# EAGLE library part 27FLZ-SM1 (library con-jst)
CONNECTOR
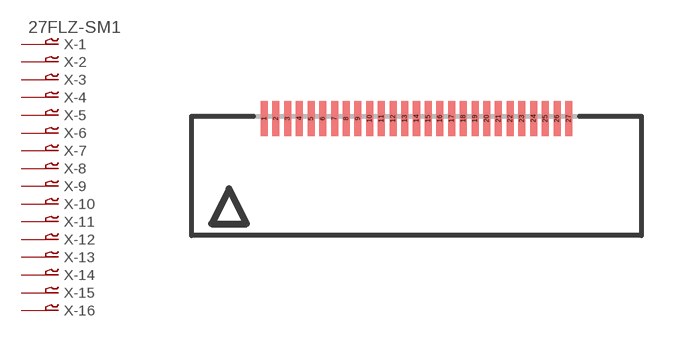
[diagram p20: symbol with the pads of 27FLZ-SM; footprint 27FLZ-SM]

Designator prefix X; gates -1=P-VN -2=P-N -3=P-N -4=P-N -5=P-N -6=P-N -7=P-N -8=P-N -9=P-N -10=P-N -11=P-N -12=P-N -13=P-N -14=P-N -15=P-N -16=P-N -17=P-N -18=P-N -19=P-N -20=P-N -21=P-N -22=P-N -23=P-N -24=P-N -25=P-N -26=P-N -27=P-N

## 27FLZ-SM1 (OC_FARNELL: unknown; OC_NEWARK: unknown)  [27FLZ-SM]
1  -1:1  pas
2  -2:1  pas
3  -3:1  pas
4  -4:1  pas
5  -5:1  pas
6  -6:1  pas
7  -7:1  pas
8  -8:1  pas
9  -9:1  pas
10  -10:1  pas
11  -11:1  pas
12  -12:1  pas
13  -13:1  pas
14  -14:1  pas
15  -15:1  pas
16  -16:1  pas
17  -17:1  pas
18  -18:1  pas
19  -19:1  pas
20  -20:1  pas
21  -21:1  pas
22  -22:1  pas
23  -23:1  pas
24  -24:1  pas
25  -25:1  pas
26  -26:1  pas
27  -27:1  pas

## Footprint 27FLZ-SM (pad centres in mm)
CONNECTOR
smd 0.3 x 1.5: 1 -6.5,2.5; 2 -6,2.5; 3 -5.5,2.5; 4 -5,2.5; 5 -4.5,2.5; 6 -4,2.5; 7 -3.5,2.5; 8 -3,2.5; 9 -2.5,2.5; 10 -2,2.5; 11 -1.5,2.5; 12 -1,2.5; 13 -0.5,2.5; 14 0,2.5; 15 0.5,2.5; 16 1,2.5; 17 1.5,2.5; 18 2,2.5; 19 2.5,2.5; 20 3,2.5; 21 3.5,2.5; 22 4,2.5; 23 4.5,2.5; 24 5,2.5; 25 5.5,2.5; 26 6,2.5; 27 6.5,2.5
